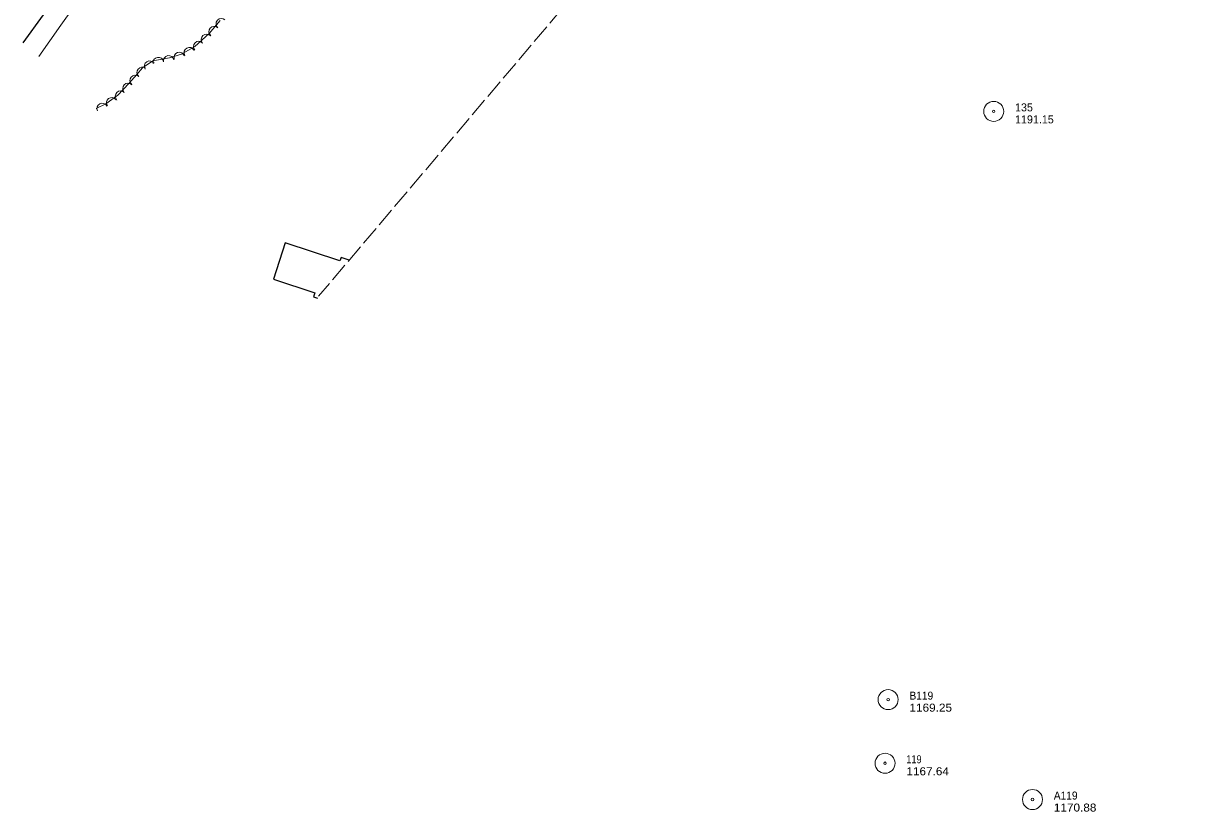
# Model space of a CAD drawing. Extents: x 301157 to 303663, y 52185 to 54539.
# Drawn here: x 302195 to 303068, y 52185 to 52776 of the extents above; entities that cross this region are included whole.
import ezdxf

# ---------------------------------------------------------------- set-up
doc = ezdxf.new("R2010")
doc.units = 0
doc.header["$LTSCALE"] = 2.4
doc.linetypes.add('LONG_DASHED', pattern=[7.5, 6, -1.5])
for name, color, linetype, lineweight in [('11', 7, 'Continuous', 25), ('12', 7, 'Continuous', 25), ('18', 7, 'Continuous', 13), ('19', 7, 'Continuous', 13), ('4', 7, 'Continuous', 13), ('6', 7, 'Continuous', 13)]:
    doc.layers.add(name, color=color, linetype=linetype, lineweight=lineweight)

msp = doc.modelspace()

# ---------------------------------------------------------------- linework, layer by layer
at = {"layer": '11'}
msp.add_lwpolyline([(302194.801, 52761.275), (302225.275, 52803.583)], dxfattribs=at)
at = {"layer": '12'}
msp.add_lwpolyline([(302439.195, 52598.619), (302433.013, 52600.636), (302432.189, 52598.11), (302391.138, 52611.504), (302382.255, 52584.279), (302413.242, 52574.169), (302412.264, 52571.171), (302415.433, 52570.137)], dxfattribs=at)
at = {"layer": '18'}
msp.add_lwpolyline([(302342.493, 52777.942), (302334.055, 52768.425), (302323.363, 52758.625), (302313.3, 52752.96), (302304.478, 52750.042), (302292.023, 52747.928), (302284.054, 52742.685), (302279.913, 52737.495), (302273.948, 52730.804), (302265.599, 52722.102), (302256.607, 52715.751), (302249.446, 52712.262)], dxfattribs=at)
for centre, start, end in [((302343.249, 52775.648), 48.4467, 228.43138), ((302337.958, 52769.68), 48.4467, 228.43138), ((302326.306, 52758.491), 42.5152, 222.49988), ((302332.186, 52763.88), 42.5152, 222.49988), ((302295.967, 52746.48), 9.64073, 189.62541), ((302303.831, 52747.815), 9.64073, 189.62541), ((302311.747, 52750.248), 18.31002, 198.29469), ((302319.248, 52753.913), 29.38514, 209.36982), ((302283.96, 52739.22), 51.42198, 231.40666), ((302289.553, 52743.804), 33.34956, 213.33424), ((302278.74, 52733.042), 48.29078, 228.27546), ((302267.774, 52721.354), 46.19366, 226.17834), ((302273.297, 52727.11), 46.19366, 226.17834), ((302253.945, 52712.132), 25.98404, 205.96872), ((302261.077, 52716.353), 35.24101, 215.22569)]:
    msp.add_arc(centre, 3.989, start, end, dxfattribs=at)
at = {"layer": '19'}
for points in [[(302206.342, 52751.117), (302222.931, 52774.632), (302241.837, 52801.257), (302267.354, 52836.585), (302289.169, 52865.452), (302307.568, 52889.693), (302319.959, 52906.804), (302328.276, 52919.248), (302340.786, 52936.703), (302353.713, 52954.734), (302365.418, 52970.878), (302375.078, 52984.583), (302390.004, 53004.394), (302399.407, 53018.737), (302411.153, 53036.094), (302423.429, 53053.35), (302435.216, 53069.439), (302441.642, 53077.498)], [(302206.342, 52751.117), (302222.931, 52774.632), (302223.162, 52774.958)]]:
    msp.add_lwpolyline(points, dxfattribs=at)
at = {"layer": '4', "linetype": 'LONG_DASHED'}
msp.add_lwpolyline([(303068.442, 53443.529), (302957.716, 53252.268), (302726.776, 52938.162), (302416.216, 52571.488)], dxfattribs=at)
at = {"layer": '6'}
for centre, radius in [((302922.272, 52709.977), 7.5), ((302922.272, 52709.977), 0.96), ((302843.126, 52269.299), 7.5), ((302843.126, 52269.299), 0.96), ((302840.811, 52221.635), 7.5), ((302840.811, 52221.635), 0.96), ((302951.345, 52194.455), 7.5), ((302951.345, 52194.455), 0.96)]:
    msp.add_circle(centre, radius, dxfattribs=at)

# ---------------------------------------------------------------- texts
for s, p in [('135', (302938.272, 52709.977)), ('1191.15', (302938.272, 52700.977))]:
    msp.add_text(s, height=6, dxfattribs=at).set_placement(p)
for s, width, p in [('B119', 0.95, (302859.126, 52269.299)), ('1169.25', 1.1, (302859.126, 52260.299)), ('119', 0.85, (302856.811, 52221.635)), ('1167.64', 1.1, (302856.811, 52212.635)), ('A119', 0.95, (302967.345, 52194.455)), ('1170.88', 1.1, (302967.345, 52185.455))]:
    msp.add_text(s, height=6, dxfattribs=dict(at, width=width)).set_placement(p)

doc.saveas('drawing.dxf')
